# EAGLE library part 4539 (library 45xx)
Dual 4-channel DATA SELECTOR/MULTIPLEXER
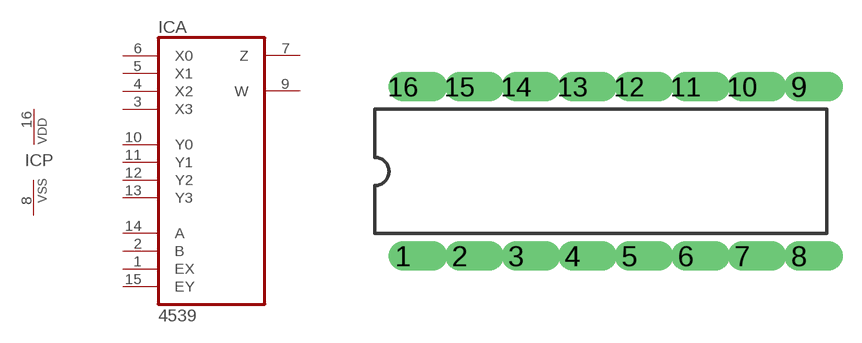
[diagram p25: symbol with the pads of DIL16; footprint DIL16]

Designator prefix IC; gates A=4539 P=PWRN

## 4539N  [DIL16]
1  A:EX  in
2  A:B  in
3  A:X3  in
4  A:X2  in
5  A:X1  in
6  A:X0  in
7  A:Z  hiz
8  P:VSS  pwr
9  A:W  hiz
10  A:Y0  in
11  A:Y1  in
12  A:Y2  in
13  A:Y3  in
14  A:A  in
15  A:EY  in
16  P:VDD  pwr

## Footprint DIL16 (pad centres in mm)
Dual In Line
drill 0.813 offset: 1 -8.89,-3.81; 2 -6.35,-3.81; 3 -3.81,-3.81; 4 -1.27,-3.81; 5 1.27,-3.81; 6 3.81,-3.81; 7 6.35,-3.81; 8 8.89,-3.81; 9 8.89,3.81; 10 6.35,3.81; 11 3.81,3.81; 12 1.27,3.81; 13 -1.27,3.81; 14 -3.81,3.81; 15 -6.35,3.81; 16 -8.89,3.81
